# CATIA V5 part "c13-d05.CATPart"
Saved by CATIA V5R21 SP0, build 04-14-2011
Part number: Part1
Bounding box of the stored display mesh (mm): x -62.5 to 62.5, y -75 to 75, z 0 to 20
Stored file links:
  D:\CATIA V5R21 E-RESOURCES\CATIA-V5R21\catia-v5r21-prt\c13-catia-v5r20-prt\c13-catia-v5r20-figr-13-18 & 20\cat_v5r21_c13-d05.CATPart
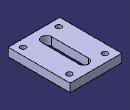
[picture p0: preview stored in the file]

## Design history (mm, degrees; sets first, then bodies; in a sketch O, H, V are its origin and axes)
Body1 (main body)
  Sketch1 on xy-plane, origin (0, 0, 0), H (1, 0, 0), V (0, 1, 0)
    line L1 (62.5, 75) -> (62.5, -75)
    line L2 (62.5, -75) -> (-62.5, -75)
    line L3 (-62.5, -75) -> (-62.5, 75)
    line L4 (-62.5, 75) -> (62.5, 75)
    length L1 = 150
    length L2 = 125
    vertical: L1 V, L3 V
    horizontal: L2 H, L4 H
    equidistance: L1 L3 O, L2 L4 O
  Pad1: profile Sketch1, direction (0, 0, 1), length 20
  Sketch2 on face of Pad1, origin (0, 0, 20), H (1, 0, 0), V (0, 1, 0)
    construction line L1 (0, 45) -> (0, -45)
    point P1 (0, 45)
    line L2 (12, 45) -> (12, -45)
    line L3 (-12, -45) -> (-12, 45)
    arc A1 centre (0, -45) radius 12 from (12, -45) to (-12, -45) cw
    arc A2 centre (0, 45) radius 12 from (-12, 45) to (12, 45) cw
    length L1 = 90
    radius A2 = 12
    coincidence: P1 V
    vertical: L1 V
    tangency: A1 L2, A2 L2, A1 L3, A2 L3
    parallelism: L1 L2
    midpoint: O L1
  Pocket1: profile Sketch2, direction (0, 0, -1), through (limit type 3)
  Sketch3 on face of Pad1, origin (38.7626, -18.4621, 20), H (1, 0, 0), V (0, 1, 0)
    point P1 (5.7374, -38.5379)
    reference projected line E1 (-101.2626, -56.5379) -> (23.7374, -56.5379) from edge [face of Pad1 | face of Pad1]
    reference projected line E2 (23.7374, -56.5379) -> (23.7374, 93.4621) from edge [face of Pad1 | face of Pad1]
    distance P1 E1 = 18
    distance P1 E2 = 18
  Hole1: placed by Sketch3, at (44.5, -57, 20) direction (0, 0, -1), diameter 13, through (limit type 3)
  RectPattern1: of Hole1, direction 1 instances 2, spacing 86, along edge [face of Pad1 | face of Pad1] reversed, direction 2 instances 2, spacing 112, along edge [face of Pad1 | face of Pad1]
